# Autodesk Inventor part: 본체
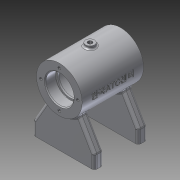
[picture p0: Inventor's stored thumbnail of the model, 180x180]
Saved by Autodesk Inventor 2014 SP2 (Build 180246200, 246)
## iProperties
Created: 2018-05
Part Number: 본체
Material: 알루미늄 6061
Document SubType Name: Modeling
Designer: 거성
Density: 2.71 g/cm^3
Appearance: 알루미늄 - 평지
Mass: 318.951 g
Surface Area: 375.774 cm^2
Volume: 117.694 cm^3
Author: 거성
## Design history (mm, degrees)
sketch "스케치1"
  geometry: L1 (-35, 91)-(35, 91); L2 (35, 91)-(35, 65); L3 (35, 65)-(-35, 65); L4 (-35, 65)-(-35, 91); 2 further points
  constraints: 8 end point, 2 parallel, 1 horizontal, 1 midpoint, 1 perpendicular, 1 vertical alignment
  dimensions: "d0" = 70 distance of L1.start L1.end; "d2" = 52 diameter of L1 L3; "d9" = 65 vertical distance of L2.end point (0, 0)
revolve "회전1" stored, may be unused: angle "d8" = 90 deg
node "작업 평면1"
sketch "스케치2"
  geometry: L1 (0, 35)-(0, -35); L2 (0, -35)-(15, -35); L3 (15, -35)-(45.614, -17.325); L4 (0, 35)-(15, 35); L5 (15, 35)-(45.614, 17.325); A1 r 26 centre (65, 0) between (45.614, -17.325) and (45.614, 17.325) reference; A2 r 26 centre (65, 0) between (45.614, 17.325) and (45.614, -17.325); 2 further points
  constraints: 10 end point, 4 point on circle, 3 coincident, 1 centre point, 1 concentric, 1 equal length, 1 midpoint, 1 parallel, 1 perpendicular, 1 vertical
  dimensions: "d11" = 70 distance of L1.start L1.end; "d12" = 30 deg angle of L5 L4; "d13" = 15 distance of L1.end L2.end; "d14" = 30 deg angle of L3 L2
extrude "돌출1" join sketch "스케치2" distance "d15" = 10; taper "d16" = 0 deg
sketch "스케치3"
  geometry: L1 (-35, 39)-(-35, 91) reference; L2 (-35, 65)-(-23, 65); L3 (-23, 65)-(-23, 81); L4 (-23, 81)-(-35, 81); L5 (-35, 81)-(-35, 65); L6 (-23, 65)-(-21, 65); L7 (-21, 65)-(-21, 79); L8 (-21, 79)-(-23, 79); L9 (-23, 79)-(-23, 65); L10 (-21, 65)-(21, 65); L11 (21, 65)-(21, 86); L12 (21, 86)-(-21, 86); L13 (-21, 86)-(-21, 65); L14 (21, 65)-(23, 65); L15 (23, 65)-(23, 79); L16 (23, 79)-(21, 79); L17 (21, 79)-(21, 65); L18 (35, 39)-(35, 91) reference; L19 (23, 65)-(35, 65); L20 (35, 65)-(35, 81); L21 (35, 81)-(23, 81); L22 (23, 81)-(23, 65); 2 further points
  constraints: 40 end point, 10 parallel, 5 horizontal, 5 perpendicular, 2 midpoint, 1 point on line, 1 vertical alignment
  dimensions: "d17" = 12 distance of L3.end L4.end; "d18" = 42 distance of L11.end L12.end; "d19" = 12 distance of L20.end L21.end; "d20" = 32 diameter of L4 L2; "d21" = 28 diameter of L8.end L2; "d22" = 42 diameter of L12 L10; "d23" = 32 diameter of L21 L19; "d24" = 28 diameter of L16 L19
revolve "회전2" sketch "스케치3" stored, may be unused: angle "d25" = 90 deg
sketch "스케치4"
  geometry: C1 r 16 at (0, 0) reference; 2 further points
  constraints: 1 vertical alignment
  dimensions: "d26" = 21 distance of C1.centre point (0, 21)
hole "구멍1" sketch "스케치4" at (0, 21) diameter "d27" = 3.242; stored, may be unused: countersink angle "d31" = 90 deg, drill point angle "d33" = 118 deg; dims "d28" = 8, "d29" = 4, "d30" = 2, "d32" = 10
sketch "스케치5"
  geometry: L1 (10, 70)-(10, 0) reference; L2 (-50, 70)-(-50, 0) reference; 5 further points
  constraints: 2 horizontal alignment, 2 vertical alignment
  dimensions: "d37" = 5 distance from line of point (-45, 15) L2; "d38" = 20 vertical distance of point (-20, 35) point (5, 55); "d39" = 40 distance of point (5, 15) point (5, 55); "d40" = 5 distance from line of point (5, 15) L1
hole "구멍2" sketch "스케치5" at (-45, 55), (-45, 15), (5, 55), (5, 15) diameter "d41" = 4.134; stored, may be unused: countersink angle "d45" = 90 deg, drill point angle "d47" = 118 deg; dims "d42" = 8, "d43" = 4, "d44" = 2, "d46" = 10
node "작업 평면2"
sketch "스케치6"
  geometry: L1 (-35, -26)-(-35, 26) reference; 2 further points
  constraints: 1 other
  dimensions: "d48" = 26 vertical distance of L1.end point (0, 0); "d49" = 35 horizontal distance of point (0, 0) L1.end
feature "엠보싱1" sketch "스케치6" dims "d0" = 70, "d2" = 52, "d9" = 65, "d50" = 0.5, "d51" = 0
node "작업 평면4"
  node "작업 평면3"
sketch "스케치7"
  geometry: C1 r 5 at (0, 0); 1 further point
  constraints: 1 centre point, 1 coincident
  dimensions: "d53" = 10 diameter of C1
extrude "돌출2" join sketch "스케치7" stored distance "d54" = 10; taper "d55" = 0 deg
hole "구멍3" diameter "d58" = 4.917; stored, may be unused: countersink angle "d62" = 90 deg, drill point angle "d64" = 118 deg; dims "d56" = 10, "d57" = 10, "d59" = 8, "d60" = 4, "d61" = 2, "d63" = 10
sketch "스케치8"
  geometry: L1 (65, 0)-(37.749, -9.919); L2 (65, 0)-(39, 0); 1 further point
  constraints: 4 end point, 1 horizontal, 1 horizontal alignment, 1 other
  dimensions: "d65" = 29 distance of L1.start L1.end; "d66" = 20 deg angle of L2 L1
node "작업 평면5"
sketch "스케치9"
  geometry: C1 r 6 at (0, 0); 4 further points
  constraints: 1 centre point, 1 coincident
  dimensions: "d67" = 12 diameter of C1
extrude "돌출3" join sketch "스케치9" stored distance "d68" = 10; taper "d69" = 0 deg
hole "구멍4" diameter "d72" = 4.917; stored, may be unused: countersink angle "d76" = 90 deg, drill point angle "d78" = 118 deg; dims "d70" = 10, "d71" = 10, "d73" = 8, "d74" = 4, "d75" = 2, "d77" = 10
fillet "모깎기1" dims "d79" = 0.3, "d80" = 3, "d81" = 2
fillet "모깎기2" dims "d82" = 3
chamfer "모따기1" distance "d83" = 1; stored, may be unused: second distance "d84" = 2, angle "d85" = 45 deg
node "솔리드1"
mirror "대칭1"
pattern_circular "원형 패턴1" dims angle "d35" = 360 deg
mirror "대칭2"
node "투영된 루프1"
other parameters: "d52" = 3
